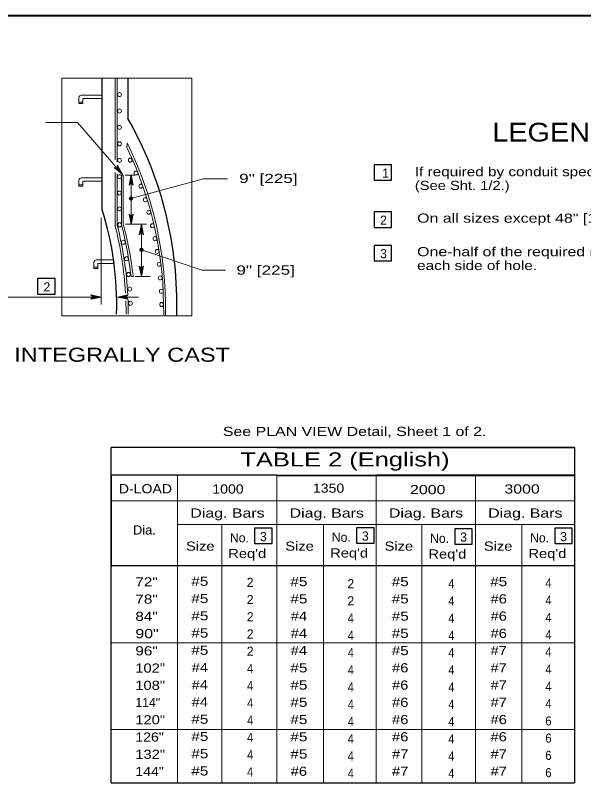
# Model space of a CAD drawing. Extents: x 1170.6 to 1204.6, y 975 to 1019.
# Drawn here: x 1189.51 to 1199.19, y 983.44 to 996.53 of the extents above; entities that cross this region are included whole.
import ezdxf
from ezdxf.enums import TextEntityAlignment as Align

# ---------------------------------------------------------------- set-up
doc = ezdxf.new("R2010")
doc.units = 0
doc.header["$LTSCALE"] = 0.062
doc.layers.add('1', color=7, linetype='Continuous', lineweight=13)

msp = doc.modelspace()

# ---------------------------------------------------------------- hatches: boundary and pattern name
at = {"layer": '1'}
for points in [[(1191.50371, 993.40632, 1), (1191.44949, 993.40632, 1)], [(1191.68403, 992.53277, 1), (1191.62811, 992.53277, 1)]]:
    msp.add_hatch(color=256, dxfattribs=at).paths.add_polyline_path(points)

# ---------------------------------------------------------------- linework, layer by layer
at = {"layer": '1', "lineweight": 25}
for p, q in [((1172.59275, 996.52625), (1204.09275, 996.52625)), ((1191.42467, 995.45017), (1191.42467, 994.76767)), ((1199.038, 989.16408), (1191.14158, 989.16408)), ((1191.14158, 987.13117), (1191.14158, 989.16408)), ((1193.956, 988.68858), (1195.65367, 988.68858)), ((1197.34583, 988.69208), (1195.64817, 988.69208)), ((1195.64817, 988.68858), (1197.34583, 988.68858)), ((1199.038, 988.69208), (1197.34042, 988.69208)), ((1197.34042, 988.68858), (1199.038, 988.68858)), ((1191.14158, 983.45158), (1191.14158, 987.13117)), ((1191.14483, 987.15483), (1199.038, 987.15483)), ((1191.14158, 983.45158), (1199.038, 983.45158))]:
    msp.add_line(p, q, dxfattribs=at)
at = {"layer": '1'}
for p, q in [((1191.20667, 994.06417), (1191.20667, 995.44525)), ((1191.24358, 994.03183), (1191.24358, 995.45017)), ((1190.99108, 995.16583), (1190.63017, 995.16583)), ((1190.99108, 995.16583), (1190.63017, 995.16583)), ((1190.59, 995.02225), (1190.59, 995.1275)), ((1190.59, 995.02225), (1190.59, 995.1275)), ((1190.59, 995.04608), (1190.65392, 995.04608)), ((1190.59, 995.04608), (1190.65392, 995.04608)), ((1190.59, 995.02225), (1190.65392, 995.02225)), ((1190.59, 995.02225), (1190.65392, 995.02225)), ((1190.65425, 995.02225), (1190.65425, 995.09542)), ((1190.65425, 995.02225), (1190.65425, 995.09542)), ((1190.99108, 995.10758), (1190.6665, 995.10758)), ((1190.99108, 995.10758), (1190.6665, 995.10758)), ((1191.40842, 994.27333), (1191.40967, 994.351)), ((1191.20667, 992.941), (1191.20667, 993.85208)), ((1191.21367, 993.92708), (1191.332, 993.81667)), ((1191.22567, 993.92983), (1191.332, 993.81667)), ((1191.23558, 993.93567), (1191.332, 993.81667)), ((1191.24492, 993.94692), (1191.332, 993.81667)), ((1191.24917, 993.95825), (1191.332, 993.81667)), ((1190.59, 993.61508), (1190.59, 993.72033)), ((1190.59, 993.61508), (1190.59, 993.72033)), ((1190.99108, 993.75867), (1190.63017, 993.75867)), ((1190.99108, 993.75867), (1190.63017, 993.75867)), ((1191.24358, 992.94392), (1191.24358, 993.82692)), ((1191.31533, 992.96225), (1191.31533, 993.8035)), ((1191.34533, 993.8035), (1191.3165, 993.8035)), ((1191.34533, 992.96967), (1191.34533, 993.8035)), ((1191.37767, 993.805), (1191.54233, 993.805)), ((1191.45467, 993.64625), (1191.47942, 993.80842)), ((1191.46508, 993.65242), (1191.47942, 993.80842)), ((1191.47658, 993.40633), (1192.71133, 993.74067)), ((1191.47942, 993.65525), (1191.47942, 993.80842)), ((1191.49075, 993.65358), (1191.47942, 993.80842)), ((1191.50183, 993.64817), (1191.47942, 993.80842)), ((1192.71133, 993.74067), (1193.12108, 993.74067)), ((1190.59, 993.63892), (1190.65392, 993.63892)), ((1190.59, 993.63892), (1190.65392, 993.63892)), ((1190.59, 993.61508), (1190.65392, 993.61508)), ((1190.59, 993.61508), (1190.65392, 993.61508)), ((1190.65425, 993.61508), (1190.65425, 993.68817)), ((1190.65425, 993.61508), (1190.65425, 993.68817)), ((1190.99108, 993.70033), (1190.6665, 993.70033)), ((1190.99108, 993.70033), (1190.6665, 993.70033)), ((1190.97092, 991.59942), (1190.97092, 993.07942)), ((1191.457, 993.125), (1191.47942, 992.96475)), ((1191.46808, 993.11958), (1191.47942, 992.96475)), ((1191.50425, 993.12692), (1191.47942, 992.96475)), ((1191.49383, 993.12075), (1191.47942, 992.96475)), ((1191.47942, 993.11792), (1191.47942, 992.96475)), ((1191.38692, 992.96742), (1191.74408, 992.96742)), ((1191.63042, 992.80533), (1191.65517, 992.96742)), ((1191.64075, 992.81142), (1191.65517, 992.96742)), ((1191.65517, 992.35508), (1191.65517, 992.96742)), ((1191.65517, 992.81425), (1191.65517, 992.96742)), ((1191.6665, 992.81267), (1191.65517, 992.96742)), ((1191.67758, 992.80717), (1191.65517, 992.96742)), ((1191.65608, 992.53275), (1192.68983, 992.18408)), ((1190.846, 992.21592), (1190.846, 992.32117)), ((1190.846, 992.21592), (1190.846, 992.32117)), ((1191.17233, 992.3595), (1190.88617, 992.3595)), ((1191.17233, 992.3595), (1190.88617, 992.3595)), ((1190.91017, 992.21592), (1190.91017, 992.289)), ((1190.91017, 992.21592), (1190.91017, 992.289)), ((1191.18117, 992.30117), (1190.9225, 992.30117)), ((1191.18117, 992.30117), (1190.9225, 992.30117)), ((1191.65517, 992.07967), (1191.65517, 992.35508)), ((1190.846, 992.23967), (1190.90992, 992.23967)), ((1190.846, 992.23967), (1190.90992, 992.23967)), ((1190.846, 992.21592), (1190.90992, 992.21592)), ((1190.846, 992.21592), (1190.90992, 992.21592)), ((1191.63275, 992.23983), (1191.65517, 992.07967)), ((1191.64383, 992.23442), (1191.65517, 992.07967)), ((1191.68, 992.24175), (1191.65517, 992.07967)), ((1191.66958, 992.23558), (1191.65517, 992.07967)), ((1191.65517, 992.23283), (1191.65517, 992.07967)), ((1192.68983, 992.18408), (1193.09, 992.18408)), ((1191.513, 992.07967), (1191.48425, 992.07967)), ((1191.54817, 992.0785), (1191.80642, 992.0785)), ((1190.81208, 991.75067), (1190.97233, 991.72825)), ((1191.40842, 991.75067), (1191.24817, 991.72825)), ((1188.66917, 991.72825), (1190.97233, 991.72825)), ((1190.81025, 991.7035), (1190.97233, 991.72825)), ((1190.81633, 991.71383), (1190.97233, 991.72825)), ((1190.8175, 991.73958), (1190.97233, 991.72825)), ((1190.81917, 991.72825), (1190.97233, 991.72825)), ((1191.403, 991.73958), (1191.24817, 991.72825)), ((1191.24817, 991.72825), (1191.60533, 991.72825)), ((1191.40133, 991.72825), (1191.24817, 991.72825)), ((1191.40417, 991.71383), (1191.24817, 991.72825)), ((1191.41025, 991.7035), (1191.24817, 991.72825)), ((1192.06717, 991.44442), (1192.06717, 991.41467)), ((1193.956, 989.16058), (1195.65367, 989.16058)), ((1195.64817, 989.16058), (1197.34583, 989.16058)), ((1197.34042, 989.16058), (1199.038, 989.16058)), ((1195.65367, 988.69208), (1193.956, 988.69208)), ((1191.14483, 988.25908), (1193.96142, 988.25908)), ((1193.956, 988.25908), (1195.65367, 988.25908)), ((1195.64817, 988.25908), (1197.34583, 988.25908)), ((1197.34042, 988.25908), (1199.038, 988.25908)), ((1192.2725, 987.85067), (1193.02375, 987.85067)), ((1193.01917, 987.85067), (1193.96467, 987.85067)), ((1193.96467, 987.85067), (1194.71592, 987.85067)), ((1194.71133, 987.85067), (1195.65683, 987.85067)), ((1195.65683, 987.85067), (1196.40817, 987.85067)), ((1196.40358, 987.85067), (1197.34908, 987.85067)), ((1196.43508, 987.84167), (1196.43508, 987.12217)), ((1197.34908, 987.85067), (1198.10033, 987.85067)), ((1198.09575, 987.85067), (1199.04125, 987.85067)), ((1196.43467, 987.14625), (1196.43467, 983.46667)), ((1191.14483, 985.84017), (1199.038, 985.84017)), ((1191.14483, 984.3595), (1199.038, 984.3595))]:
    msp.add_line(p, q, dxfattribs=at)
at = {"layer": '1', "lineweight": 40}
msp.add_lwpolyline([(1172.59275, 996.52625), (1204.09275, 996.52625), (1204.09275, 975.52625), (1172.59275, 975.52625)], close=True, dxfattribs=at)
at = {"layer": '1'}
msp.add_lwpolyline([(1190.29917, 995.45783), (1192.51558, 995.45783), (1192.51558, 991.4065), (1190.29917, 991.4065)], close=True, dxfattribs=at)
at = {"layer": '1', "lineweight": 25}
for points in [[(1190.98758, 993.21117), (1190.98758, 993.98508), (1190.98758, 995.45017)], [(1199.038, 989.16408), (1199.038, 987.13117), (1199.038, 983.45158)], [(1193.96142, 988.69208), (1191.14158, 988.69208), (1191.14158, 987.13117)]]:
    msp.add_lwpolyline(points, dxfattribs=at)
at = {"layer": '1'}
for points in [[(1191.332, 993.81667), (1190.5675, 994.704), (1190.02458, 994.704)], [(1191.248, 993.9765), (1191.332, 993.81667), (1191.193, 993.93192)], [(1191.444, 993.63142), (1191.47942, 993.80842), (1191.51483, 993.63142)], [(1191.47942, 992.96475), (1191.47942, 993.24642), (1191.47942, 993.80842)], [(1191.51483, 993.14175), (1191.47942, 992.96475), (1191.444, 993.14175)], [(1191.61975, 992.79042), (1191.65517, 992.96742), (1191.69058, 992.79042)], [(1191.69058, 992.25667), (1191.65517, 992.07967), (1191.61975, 992.25667)], [(1190.79533, 991.69283), (1190.97233, 991.72825), (1190.79533, 991.76367)], [(1191.42517, 991.69283), (1191.24817, 991.72825), (1191.42517, 991.76367)], [(1192.2725, 988.69208), (1192.2725, 987.13117), (1192.2725, 983.45158)], [(1193.96467, 988.69208), (1193.96467, 987.13117), (1193.96467, 983.45158)], [(1195.65683, 988.69208), (1195.65683, 987.13117), (1195.65683, 983.45158)], [(1197.34908, 988.69208), (1197.34908, 987.13117), (1197.34908, 983.45158)], [(1193.02375, 987.85067), (1193.02375, 987.13117), (1193.02375, 983.45158)], [(1194.76092, 987.85967), (1194.76092, 987.14017), (1194.76092, 983.46058)], [(1198.13967, 987.85067), (1198.13967, 987.13117), (1198.13967, 983.45158)]]:
    msp.add_lwpolyline(points, dxfattribs=at)
at = {"layer": '1', "lineweight": 25}
for points in [[(1195.6205, 993.98092), (1195.6205, 993.71942), (1195.91908, 993.71942), (1195.91908, 993.98092)], [(1195.6205, 993.17675), (1195.6205, 992.915), (1195.91908, 992.915), (1195.91908, 993.17675)], [(1195.6205, 992.607), (1195.6205, 992.34525), (1195.91908, 992.34525), (1195.91908, 992.607)], [(1189.88458, 992.04142), (1189.88458, 991.77967), (1190.18325, 991.77967), (1190.18325, 992.04142)], [(1193.58408, 987.7895), (1193.58408, 987.52775), (1193.88267, 987.52775), (1193.88267, 987.7895)], [(1195.32125, 987.7985), (1195.32125, 987.53675), (1195.61983, 987.53675), (1195.61983, 987.7985)], [(1196.99542, 987.7805), (1196.99542, 987.51875), (1197.29408, 987.51875), (1197.29408, 987.7805)], [(1198.7, 987.7895), (1198.7, 987.52775), (1198.99858, 987.52775), (1198.99858, 987.7895)]]:
    msp.add_lwpolyline(points, close=True, dxfattribs=at)
at = {"layer": '1'}
for centre, radius in [((1191.4766, 993.40632), 0.0295), ((1191.4766, 993.40632), 0.02711), ((1191.65607, 992.53277), 0.0295), ((1191.65607, 992.53277), 0.02796)]:
    msp.add_circle(centre, radius, dxfattribs=at)
for centre, start, end in [((1191.2115, 993.96526), 241.12811, 16.95424), ((1191.47948, 993.61709), 22.08782, 157.91395), ((1191.4794, 993.15608), 202.08782, 337.91395), ((1191.65522, 992.77615), 22.08782, 157.91395), ((1191.65514, 992.27092), 202.08782, 337.91395), ((1190.78106, 991.72829), 292.08605, 67.91218), ((1191.43945, 991.72829), 112.08782, 247.91395)]:
    msp.add_arc(centre, 0.0382, start, end, dxfattribs=at)
for centre, major_axis, start_param, end_param in [((1190.63111, 995.12207), (0, 0.04383), 0.02303975, 1.4456919), ((1190.63111, 995.12207), (0, 0.04383), 0.02303975, 1.4456919), ((1190.66578, 995.09534), (0, 0.01224), 6.2212346, 7.84973137), ((1190.66578, 995.09534), (0, 0.01224), 6.2212346, 7.84973137), ((1186.27375, 991.50662), (0, 6.09972), 4.69880145, 5.18317196), ((1186.30624, 991.52728), (0, 6.09972), 4.69880145, 5.19464595), ((1190.63111, 993.71488), (0, 0.04383), 0.02303975, 1.4456919), ((1190.63111, 993.71488), (0, 0.04383), 0.02303975, 1.4456919), ((1190.66578, 993.68815), (0, 0.01224), 6.2212346, 7.84973137), ((1190.66578, 993.68815), (0, 0.01224), 6.2212346, 7.84973137), ((1186.07948, 991.46171), (0, 5.62619), 4.77126844, 4.97966138), ((1186.11646, 991.46662), (0, 5.62619), 4.76476641, 4.9782927), ((1185.70436, 991.34432), (0, 6.15681), 4.83210397, 4.97830395), ((1186.77149, 991.54106), (0, 5.04871), 4.8192662, 4.99927893), ((1190.88709, 992.31569), (0, 0.04383), 0.02303975, 1.4456919), ((1190.88709, 992.31569), (0, 0.04383), 0.02303975, 1.4456919), ((1190.92176, 992.28895), (0, 0.01224), 6.2212346, 7.84973137), ((1190.92176, 992.28895), (0, 0.01224), 6.2212346, 7.84973137), ((1186.07948, 991.46171), (0, 5.62619), 4.70771426, 4.74861891), ((1186.11646, 991.46662), (0, 5.62619), 4.70684072, 4.75282797)]:
    msp.add_ellipse(centre, major_axis=major_axis, ratio=0.944544, start_param=start_param, end_param=end_param, dxfattribs=at)
for centre in [(1191.28262, 995.17709), (1191.28262, 994.89725), (1191.28262, 994.61741), (1191.28262, 994.33758), (1191.28262, 994.05774), (1191.46528, 994.05949), (1191.56235, 993.83911), (1191.28262, 993.7779), (1191.64558, 993.61632), (1191.28033, 993.49873), (1191.72189, 993.38612), (1191.28262, 993.22938), (1191.78199, 993.17308), (1191.2849, 992.95754), (1191.84209, 992.94296), (1191.34728, 992.66138), (1191.88599, 992.72251), (1191.92296, 992.50455), (1191.40054, 992.37962), (1191.95758, 992.28659), (1191.43523, 992.11261), (1191.97614, 992.05397), (1191.45836, 991.86533), (1191.99463, 991.82619), (1191.46756, 991.62039), (1191.99927, 991.6009)]:
    msp.add_ellipse(centre, major_axis=(0, 0.03466), ratio=0.944544, dxfattribs=at)
at = {"layer": '1', "lineweight": 25}
for centre, major_axis, start_param, end_param in [((1186.4989, 991.60373), (0, 6.09972), 4.68171734, 5.25771769), ((1186.49496, 991.61464), (0, 5.01725), 4.67717352, 5.0362132)]:
    msp.add_ellipse(centre, major_axis=major_axis, ratio=0.944544, start_param=start_param, end_param=end_param, dxfattribs=at)

# ---------------------------------------------------------------- texts
at = {"layer": '1'}
for s, height, width, p in [('LEGEND', 0.32, 1.15, (1197.63375, 994.37642)), ('If required by conduit specification.', 0.156, 1.25, (1196.31558, 993.78533)), ('(See Sht. 1/2.)', 0.156, 1.2, (1196.31558, 993.55133)), ('On all sizes except 48" [1200].', 0.156, 1.3, (1196.35492, 992.99442)), ('One-half of the required number to', 0.156, 1.3, (1196.354, 992.42292)), ('each side of hole. ', 0.156, 1.25, (1196.354, 992.18825)), ('INTEGRALLY CAST', 0.24, 1.25, (1189.48692, 990.62525)), ('See PLAN VIEW Detail, Sheet 1 of 2.', 0.156, 1.3, (1193.04317, 989.36092)), ('TABLE 2 (English)', 0.24, 1.35, (1193.34367, 988.84275)), ('D-LOAD', 0.156, 1.15, (1191.27033, 988.38475)), ('1000', 0.156, 1.15, (1192.86392, 988.38058)), ('1350', 0.156, 1.15, (1194.57792, 988.39458)), ('2000', 0.156, 1.3, (1196.23292, 988.37067)), ('3000', 0.156, 1.3, (1197.84125, 988.38058)), ('Diag. Bars', 0.156, 1.3, (1192.48875, 987.97083)), ('Diag. Bars', 0.156, 1.3, (1194.18092, 987.97083)), ('Diag. Bars', 0.156, 1.3, (1195.87308, 987.97083)), ('Diag. Bars', 0.156, 1.3, (1197.56533, 987.97083)), ('Dia.', 0.156, 1.05, (1191.51158, 987.68275)), ('Size', 0.156, 1.2, (1192.41492, 987.40692)), ('Size', 0.156, 1.2, (1194.10717, 987.40692)), ('Size', 0.156, 1.2, (1195.79933, 987.40692)), ('Size', 0.156, 1.2, (1197.4915, 987.40692)), ("Req'd", 0.156, 1.2, (1193.13508, 987.28167)), ("Req'd", 0.156, 1.2, (1194.87225, 987.29067)), ("Req'd", 0.156, 1.2, (1196.54642, 987.27267)), ("Req'd", 0.156, 1.2, (1198.251, 987.28167)), ('72"', 0.156, 1.25, (1191.55183, 986.79817)), ('78"', 0.156, 1.25, (1191.55183, 986.5045)), ('84"', 0.156, 1.25, (1191.55183, 986.21083)), ('90"', 0.156, 1.3, (1191.55183, 985.91717)), ('96"', 0.156, 1.25, (1191.55183, 985.6235)), ('102"', 0.156, 1.2, (1191.55183, 985.32983)), ('108"', 0.156, 1.2, (1191.55183, 985.03617)), ('120"', 0.156, 1.2, (1191.55183, 984.44883)), ('126"', 0.156, 1.15, (1191.55183, 984.15517)), ('132"', 0.156, 1.2, (1191.55183, 983.8615)), ('144"', 0.156, 1.15, (1191.55183, 983.56783))]:
    msp.add_text(s, height=height, dxfattribs=dict(at, width=width)).set_placement(p)
for s, p in [('1', (1195.75925, 993.76183)), ('2', (1195.72242, 992.9585)), ('3', (1195.72242, 992.38875)), ('2', (1189.9865, 991.82325)), ('No.', (1193.163, 987.54925)), ('3', (1193.67625, 987.56967)), ('No.', (1194.90017, 987.55825)), ('3', (1195.41342, 987.57875)), ('No.', (1196.57433, 987.54025)), ('3', (1197.08758, 987.56067)), ('No.', (1198.27892, 987.54925)), ('3', (1198.79217, 987.56967)), ('114"', (1191.55183, 984.7425))]:
    msp.add_text(s, height=0.156, dxfattribs=at).set_placement(p)
for s, width, p in [('9" [225]', 1.4, (1193.81921, 993.67067)), ('9" [225]', 1.4, (1193.77304, 992.10933)), ('#5', 1.25, (1192.65104, 986.80817)), ('#5', 1.25, (1194.33912, 986.80242)), ('#5', 1.25, (1196.06629, 986.80242)), ('4', 0.9, (1196.93837, 986.76792)), ('#5', 1.25, (1197.74454, 986.80242)), ('4', 0.9, (1198.59212, 986.77942)), ('#5', 1.25, (1192.65104, 986.5145)), ('#5', 1.25, (1194.33912, 986.50875)), ('#5', 1.25, (1196.06629, 986.50875)), ('#6', 1.2, (1197.7445, 986.50875)), ('4', 0.9, (1196.93837, 986.47425)), ('4', 0.9, (1198.59212, 986.48575)), ('#5', 1.25, (1192.65104, 986.22083)), ('#4', 1.2, (1194.33908, 986.21508)), ('4', 0.9, (1195.22346, 986.18058)), ('#5', 1.25, (1196.06629, 986.21508)), ('4', 0.9, (1196.93837, 986.18058)), ('#6', 1.2, (1197.7445, 986.21508)), ('4', 0.9, (1198.59212, 986.19208)), ('#5', 1.25, (1192.65104, 985.92717)), ('#4', 1.2, (1194.33908, 985.92142)), ('4', 0.9, (1195.22346, 985.88692)), ('#5', 1.25, (1196.06629, 985.92142)), ('4', 0.9, (1196.93837, 985.88692)), ('#6', 1.2, (1197.7445, 985.92142)), ('4', 0.9, (1198.59212, 985.89842)), ('#5', 1.25, (1192.65104, 985.6335)), ('#4', 1.2, (1194.33908, 985.62775)), ('4', 0.9, (1195.22346, 985.59325)), ('#5', 1.25, (1196.06629, 985.62775)), ('4', 0.9, (1196.93837, 985.59325)), ('#7', 1.2, (1197.74454, 985.62775)), ('4', 0.9, (1198.59212, 985.60475)), ('#4', 1.2, (1192.651, 985.33983)), ('4', 0.9, (1193.50846, 985.32258)), ('#5', 1.25, (1194.33912, 985.33408)), ('#6', 1.2, (1196.06625, 985.33408)), ('#7', 1.2, (1197.74454, 985.33408)), ('4', 0.9, (1198.59212, 985.31108)), ('4', 0.9, (1195.22346, 985.29958)), ('4', 0.9, (1196.93837, 985.29958)), ('#4', 1.2, (1192.651, 985.04617)), ('4', 0.9, (1193.50846, 985.02892)), ('#5', 1.25, (1194.33912, 985.04042)), ('4', 0.9, (1195.22346, 985.00592)), ('#6', 1.2, (1196.06625, 985.04042)), ('4', 0.9, (1196.93837, 985.00592)), ('#7', 1.2, (1197.74454, 985.04042)), ('4', 0.9, (1198.59212, 985.01742)), ('#4', 1.2, (1192.651, 984.7525)), ('4', 0.9, (1193.50846, 984.73525)), ('#5', 1.25, (1194.33912, 984.74675)), ('4', 0.9, (1195.22346, 984.71225)), ('#6', 1.2, (1196.06625, 984.74675)), ('4', 0.9, (1196.93837, 984.71225)), ('#7', 1.2, (1197.74454, 984.74675)), ('4', 0.9, (1198.59212, 984.72375)), ('#5', 1.25, (1192.65104, 984.45883)), ('4', 0.9, (1193.50846, 984.44158)), ('#5', 1.25, (1194.33912, 984.45308)), ('4', 0.9, (1195.22346, 984.41858)), ('#6', 1.2, (1196.06625, 984.45308)), ('4', 0.9, (1196.93837, 984.41858)), ('#6', 1.2, (1197.7445, 984.45308)), ('6', 0.9, (1198.59212, 984.43008)), ('#5', 1.25, (1192.65104, 984.16517)), ('4', 0.9, (1193.50846, 984.14792)), ('#5', 1.25, (1194.33912, 984.15942)), ('#6', 1.2, (1196.06625, 984.15942)), ('#6', 1.2, (1197.7445, 984.15942)), ('6', 0.9, (1198.59212, 984.13642)), ('4', 0.9, (1195.22346, 984.12492)), ('4', 0.9, (1196.93837, 984.12492)), ('#5', 1.25, (1192.65104, 983.8715)), ('4', 0.9, (1193.50846, 983.85425)), ('#5', 1.25, (1194.33912, 983.86575)), ('4', 0.9, (1195.22346, 983.83125)), ('#7', 1.2, (1196.06629, 983.86575)), ('4', 0.9, (1196.93837, 983.83125)), ('#7', 1.2, (1197.74454, 983.86575)), ('6', 0.9, (1198.59212, 983.84275)), ('#5', 1.25, (1192.65104, 983.57783)), ('4', 0.9, (1193.50846, 983.56058)), ('#6', 1.2, (1194.33908, 983.57208)), ('4', 0.9, (1195.22346, 983.53758)), ('#7', 1.2, (1196.06629, 983.57208)), ('4', 0.9, (1196.93837, 983.53758)), ('#7', 1.2, (1197.74454, 983.57208)), ('6', 0.9, (1198.59212, 983.54908))]:
    msp.add_text(s, height=0.156, dxfattribs=dict(at, width=width)).set_placement(p, align=Align.CENTER)
for p in [(1193.50854, 986.79092), (1195.22354, 986.76792), (1193.50854, 986.49725), (1195.22354, 986.47425), (1193.50854, 986.20358), (1193.50854, 985.90992), (1193.50854, 985.61625)]:
    msp.add_text('2', height=0.156, dxfattribs=at).set_placement(p, align=Align.CENTER)

doc.saveas('drawing.dxf')
